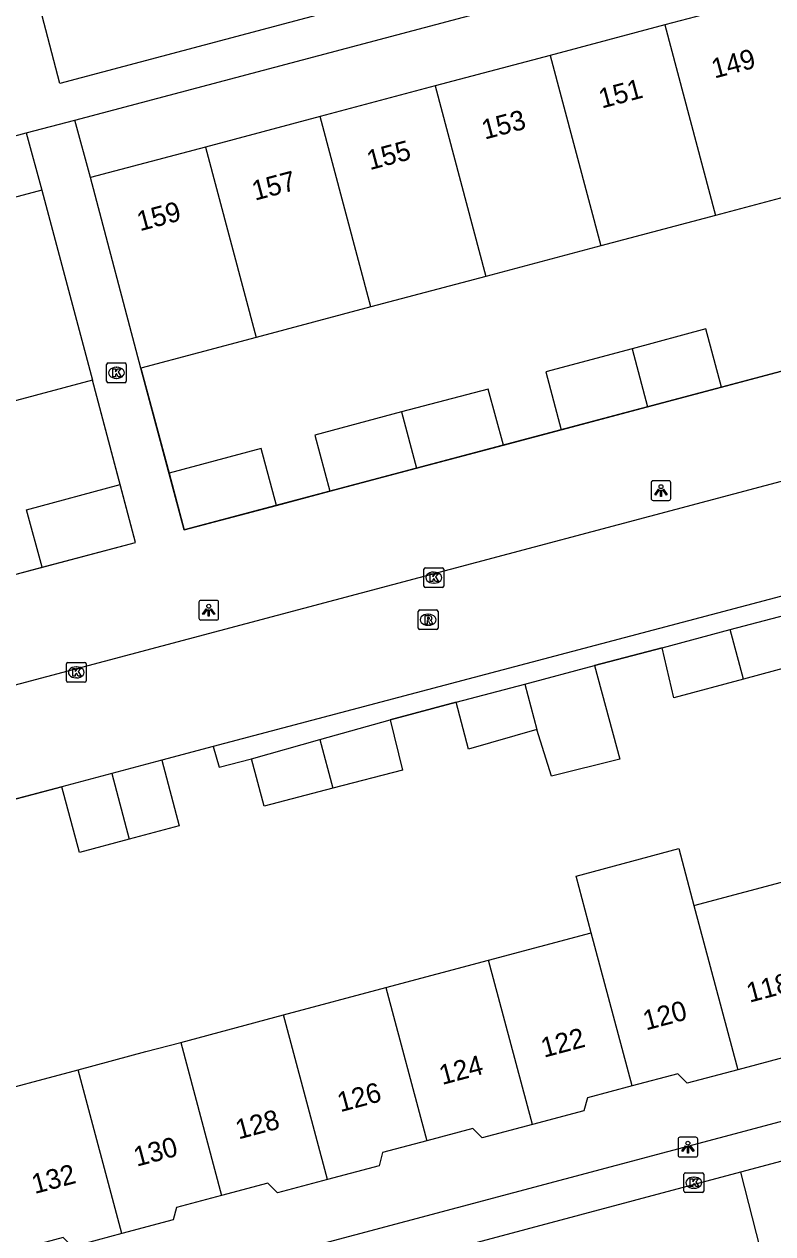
# Model space of a CAD drawing. Extents: x 162542 to 163144, y 380786 to 381511.
# Drawn here: x 162693.7 to 162731.7, y 381045.2 to 381106.6 of the extents above; entities that cross this region are included whole.
import ezdxf

# ---------------------------------------------------------------- set-up
doc = ezdxf.new("R2010")
doc.units = 0
for name, color, linetype in [('IMGEO_Kolk', 7, 'Continuous'), ('IMGEO_Lichtpunt', 7, 'Continuous'), ('IMGEO_Muur', 7, 'Continuous'), ('IMGEO_Pand', 7, 'Continuous'), ('IMGEO_Pand_nummerreeks', 7, 'Continuous'), ('IMGEO_Rijbaan_lokaal_open', 7, 'Continuous'), ('IMGEO_Rioolput', 7, 'Continuous'), ('IMGEO_Voetpad_open', 7, 'Continuous')]:
    doc.layers.add(name, color=color, linetype=linetype)

msp = doc.modelspace()

# ---------------------------------------------------------------- linework, layer by layer
at = {"layer": 'IMGEO_Kolk'}
for p, q in [((162697.906, 381088.473), (162697.906, 381089.325)), ((162697.981, 381089.399), (162698.833, 381089.399)), ((162698.394, 381089.179), (162698.419, 381089.179)), ((162698.907, 381089.325), (162698.907, 381088.473)), ((162698.417, 381088.619), (162698.392, 381088.619)), ((162698.833, 381088.399), (162697.981, 381088.399)), ((162713.998, 381078.083), (162713.998, 381078.935)), ((162714.073, 381079.009), (162714.925, 381079.009)), ((162714.486, 381078.789), (162714.511, 381078.789)), ((162714.999, 381078.935), (162714.999, 381078.083)), ((162714.925, 381078.009), (162714.073, 381078.009)), ((162714.509, 381078.229), (162714.484, 381078.229)), ((162695.868, 381073.28), (162695.868, 381074.132)), ((162695.943, 381074.206), (162696.795, 381074.206)), ((162696.356, 381073.986), (162696.381, 381073.986)), ((162696.869, 381074.132), (162696.869, 381073.28)), ((162696.795, 381073.206), (162695.943, 381073.206)), ((162696.379, 381073.426), (162696.354, 381073.426)), ((162727.182, 381047.392), (162727.182, 381048.244)), ((162727.257, 381048.318), (162728.109, 381048.318)), ((162727.67, 381048.098), (162727.695, 381048.098)), ((162728.183, 381048.244), (162728.183, 381047.392)), ((162728.109, 381047.318), (162727.257, 381047.318)), ((162727.693, 381047.538), (162727.668, 381047.538))]:
    msp.add_line(p, q, dxfattribs=at)
for points in [[(162697.906, 381088.473), (162697.906, 381089.325)], [(162697.981, 381089.399), (162698.833, 381089.399)], [(162698.227, 381089.099), (162698.35, 381089.099), (162698.35, 381088.948), (162698.48, 381089.099), (162698.644, 381089.099), (162698.498, 381088.948), (162698.651, 381088.699), (162698.499, 381088.699), (162698.414, 381088.863), (162698.35, 381088.796), (162698.35, 381088.699), (162698.227, 381088.699), (162698.227, 381089.099)], [(162698.907, 381089.325), (162698.907, 381088.473)], [(162698.833, 381088.399), (162697.981, 381088.399)], [(162713.998, 381078.083), (162713.998, 381078.935)], [(162714.073, 381079.009), (162714.925, 381079.009)], [(162714.319, 381078.709), (162714.442, 381078.709), (162714.442, 381078.558), (162714.572, 381078.709), (162714.736, 381078.709), (162714.59, 381078.558), (162714.743, 381078.309), (162714.591, 381078.309), (162714.506, 381078.473), (162714.442, 381078.406), (162714.442, 381078.309), (162714.319, 381078.309), (162714.319, 381078.709)], [(162714.999, 381078.935), (162714.999, 381078.083)], [(162714.925, 381078.009), (162714.073, 381078.009)], [(162695.868, 381073.28), (162695.868, 381074.132)], [(162695.943, 381074.206), (162696.795, 381074.206)], [(162696.189, 381073.906), (162696.312, 381073.906), (162696.312, 381073.755), (162696.442, 381073.906), (162696.606, 381073.906), (162696.46, 381073.755), (162696.613, 381073.506), (162696.461, 381073.506), (162696.376, 381073.67), (162696.312, 381073.603), (162696.312, 381073.506), (162696.189, 381073.506), (162696.189, 381073.906)], [(162696.869, 381074.132), (162696.869, 381073.28)], [(162696.795, 381073.206), (162695.943, 381073.206)], [(162727.182, 381047.392), (162727.182, 381048.244)], [(162727.257, 381048.318), (162728.109, 381048.318)], [(162727.503, 381048.018), (162727.626, 381048.018), (162727.626, 381047.867), (162727.756, 381048.018), (162727.92, 381048.018), (162727.774, 381047.867), (162727.927, 381047.618), (162727.775, 381047.618), (162727.69, 381047.782), (162727.626, 381047.715), (162727.626, 381047.618), (162727.503, 381047.618), (162727.503, 381048.018)], [(162728.183, 381048.244), (162728.183, 381047.392)], [(162728.109, 381047.318), (162727.257, 381047.318)]]:
    msp.add_lwpolyline(points, dxfattribs=at)
for centre, start, end in [((162697.983, 381089.323), 91.55205, 178.44795), ((162697.983, 381089.323), 91.55205, 178.44795), ((162698.831, 381089.323), 1.55205, 88.44795), ((162698.831, 381089.323), 1.55205, 88.44795), ((162697.983, 381088.475), 181.55205, 268.44795), ((162697.983, 381088.475), 181.55205, 268.44795), ((162698.831, 381088.475), 271.55205, 358.44795), ((162698.831, 381088.475), 271.55205, 358.44795), ((162714.075, 381078.933), 91.55205, 178.44795), ((162714.075, 381078.933), 91.55205, 178.44795), ((162714.923, 381078.933), 1.55205, 88.44795), ((162714.923, 381078.933), 1.55205, 88.44795), ((162714.075, 381078.085), 181.55205, 268.44795), ((162714.075, 381078.085), 181.55205, 268.44795), ((162714.923, 381078.085), 271.55205, 358.44795), ((162714.923, 381078.085), 271.55205, 358.44795), ((162695.945, 381074.13), 91.55205, 178.44795), ((162695.945, 381074.13), 91.55205, 178.44795), ((162696.793, 381074.13), 1.55205, 88.44795), ((162696.793, 381074.13), 1.55205, 88.44795), ((162695.945, 381073.282), 181.55205, 268.44795), ((162695.945, 381073.282), 181.55205, 268.44795), ((162696.793, 381073.282), 271.55205, 358.44795), ((162696.793, 381073.282), 271.55205, 358.44795), ((162727.259, 381048.242), 91.55205, 178.44795), ((162727.259, 381048.242), 91.55205, 178.44795), ((162728.107, 381048.242), 1.55205, 88.44795), ((162728.107, 381048.242), 1.55205, 88.44795), ((162727.259, 381047.394), 181.55205, 268.44795), ((162727.259, 381047.394), 181.55205, 268.44795), ((162728.107, 381047.394), 271.55205, 358.44795), ((162728.107, 381047.394), 271.55205, 358.44795)]:
    msp.add_arc(centre, 0.0765, start, end, dxfattribs=at)
for centre, major_axis, ratio, start_param, end_param in [((162698.393, 381088.899), (-0.387, 0.002), 0.722429, 4.712389, 7.853982), ((162698.418, 381088.899), (-0.39, 0.002), 0.717154, 1.570796, 4.712389), ((162714.485, 381078.509), (-0.387, 0.002), 0.722429, 4.712389, 7.853982), ((162714.51, 381078.509), (-0.39, 0.002), 0.717154, 1.570796, 4.712389), ((162696.355, 381073.706), (-0.387, 0.002), 0.722429, 4.712389, 7.853982), ((162696.38, 381073.706), (-0.39, 0.002), 0.717154, 1.570796, 4.712389), ((162727.669, 381047.818), (-0.387, 0.002), 0.722429, 4.712389, 7.853982), ((162727.694, 381047.818), (-0.39, 0.002), 0.717154, 1.570796, 4.712389)]:
    msp.add_ellipse(centre, major_axis=major_axis, ratio=ratio, start_param=start_param, end_param=end_param, dxfattribs=at)
at = {"layer": 'IMGEO_Lichtpunt'}
for p, q in [((162725.517, 381083.327), (162725.517, 381082.52)), ((162725.517, 381083.327), (162725.517, 381082.52)), ((162726.419, 381083.422), (162725.611, 381083.422)), ((162726.419, 381083.422), (162725.611, 381083.422)), ((162726.513, 381082.52), (162726.513, 381083.327)), ((162726.513, 381082.52), (162726.513, 381083.327)), ((162725.611, 381082.426), (162726.419, 381082.426)), ((162725.611, 381082.426), (162726.419, 381082.426)), ((162702.588, 381077.262), (162702.588, 381076.455)), ((162702.588, 381077.262), (162702.588, 381076.455)), ((162703.49, 381077.357), (162702.682, 381077.357)), ((162703.49, 381077.357), (162702.682, 381077.357)), ((162703.584, 381076.455), (162703.584, 381077.262)), ((162703.584, 381076.455), (162703.584, 381077.262)), ((162702.682, 381076.361), (162703.49, 381076.361)), ((162702.682, 381076.361), (162703.49, 381076.361)), ((162726.88, 381050.026), (162726.88, 381049.219)), ((162726.88, 381050.026), (162726.88, 381049.219)), ((162727.782, 381050.121), (162726.974, 381050.121)), ((162727.782, 381050.121), (162726.974, 381050.121)), ((162727.876, 381049.219), (162727.876, 381050.026)), ((162727.876, 381049.219), (162727.876, 381050.026)), ((162726.974, 381049.125), (162727.782, 381049.125)), ((162726.974, 381049.125), (162727.782, 381049.125))]:
    msp.add_line(p, q, dxfattribs=at)
for points in [[(162725.891, 381082.991), (162725.93, 381082.963), (162725.742, 381082.701), (162725.704, 381082.728), (162725.891, 381082.991)], [(162725.993, 381082.943), (162726.04, 381082.943), (162726.04, 381082.621), (162725.993, 381082.621), (162725.993, 381082.943)], [(162726.103, 381082.963), (162726.141, 381082.99), (162726.328, 381082.728), (162726.289, 381082.7), (162726.103, 381082.963)], [(162702.962, 381076.926), (162703.001, 381076.898), (162702.813, 381076.636), (162702.775, 381076.663), (162702.962, 381076.926)], [(162703.064, 381076.878), (162703.111, 381076.878), (162703.111, 381076.556), (162703.064, 381076.556), (162703.064, 381076.878)], [(162703.174, 381076.898), (162703.212, 381076.925), (162703.399, 381076.663), (162703.36, 381076.635), (162703.174, 381076.898)], [(162727.254, 381049.69), (162727.293, 381049.662), (162727.105, 381049.4), (162727.067, 381049.427), (162727.254, 381049.69)], [(162727.356, 381049.642), (162727.403, 381049.642), (162727.403, 381049.32), (162727.356, 381049.32), (162727.356, 381049.642)], [(162727.466, 381049.662), (162727.504, 381049.689), (162727.691, 381049.427), (162727.652, 381049.399), (162727.466, 381049.662)]]:
    msp.add_lwpolyline(points, dxfattribs=at)
for centre in [(162726.016, 381083.125), (162703.087, 381077.06), (162727.379, 381049.824)]:
    msp.add_circle(centre, 0.0994, dxfattribs=at)
for centre, start, end in [((162725.611, 381083.327), 90, 180), ((162725.611, 381083.327), 90, 180), ((162726.419, 381083.327), 0, 90), ((162726.419, 381083.327), 0, 90), ((162725.611, 381082.52), 180, 270), ((162725.611, 381082.52), 180, 270), ((162726.419, 381082.52), 270, 0), ((162726.419, 381082.52), 270, 360), ((162702.682, 381077.262), 90, 180), ((162702.682, 381077.262), 90, 180), ((162703.49, 381077.262), 0, 90), ((162703.49, 381077.262), 0, 90), ((162702.682, 381076.455), 180, 270), ((162702.682, 381076.455), 180, 270), ((162703.49, 381076.455), 270, 0), ((162703.49, 381076.455), 270, 360), ((162726.974, 381050.026), 90, 180), ((162726.974, 381050.026), 90, 180), ((162727.782, 381050.026), 0, 90), ((162727.782, 381050.026), 0, 90), ((162726.974, 381049.219), 180, 270), ((162726.974, 381049.219), 180, 270), ((162727.782, 381049.219), 270, 0), ((162727.782, 381049.219), 270, 360)]:
    msp.add_arc(centre, 0.0946, start, end, dxfattribs=at)
at = {"layer": 'IMGEO_Muur'}
for points in [[(162772.214, 381096.585), (162766.422, 381095.044), (162765.622, 381097.877), (162701.846, 381080.936)], [(162701.846, 381080.936), (162699.651, 381089.143)], [(162699.379, 381080.297), (162697.197, 381088.519)], [(162676.192, 381074.139), (162699.379, 381080.297)], [(162726.075, 381074.957), (162722.642, 381074.047)], [(162715.625, 381072.185), (162712.292, 381071.3)], [(162703.608, 381068.898), (162705.262, 381069.324)], [(162692.811, 381067.153), (162695.613, 381067.899)]]:
    msp.add_lwpolyline(points, dxfattribs=at)
at = {"layer": 'IMGEO_Pand'}
for points in [[(162732.042, 381108.097), (162726.216, 381106.548)], [(162726.216, 381106.548), (162720.391, 381104.999)], [(162726.216, 381106.548), (162728.785, 381096.887)], [(162720.391, 381104.999), (162714.565, 381103.451)], [(162720.391, 381104.999), (162722.959, 381095.339)], [(162714.565, 381103.451), (162708.739, 381101.902)], [(162714.565, 381103.451), (162717.134, 381093.79)], [(162708.739, 381101.902), (162702.914, 381100.353)], [(162711.308, 381092.241), (162708.739, 381101.902)], [(162702.914, 381100.353), (162697.083, 381098.802)], [(162702.914, 381100.353), (162705.482, 381090.693)], [(162699.651, 381089.143), (162697.083, 381098.802)], [(162734.611, 381098.436), (162728.785, 381096.887)], [(162694.624, 381098.159), (162688.799, 381096.606)], [(162694.624, 381098.159), (162697.197, 381088.519)], [(162728.785, 381096.887), (162722.959, 381095.339)], [(162722.959, 381095.339), (162717.134, 381093.79)], [(162717.134, 381093.79), (162711.308, 381092.241)], [(162711.308, 381092.241), (162705.482, 381090.693)], [(162729.082, 381088.171), (162728.289, 381091.13), (162724.548, 381090.117)], [(162705.482, 381090.693), (162699.651, 381089.143)], [(162724.548, 381090.117), (162720.171, 381088.943), (162720.958, 381086.013)], [(162724.548, 381090.117), (162725.331, 381087.174)], [(162697.197, 381088.519), (162691.363, 381086.964)], [(162718.023, 381085.233), (162717.261, 381088.078), (162712.865, 381086.914)], [(162725.331, 381087.174), (162729.082, 381088.171)], [(162712.865, 381086.914), (162708.467, 381085.734), (162709.227, 381082.897)], [(162712.865, 381086.914), (162713.622, 381084.064)], [(162720.958, 381086.013), (162725.331, 381087.174)], [(162706.517, 381082.177), (162705.745, 381085.057), (162701.078, 381083.807)], [(162713.622, 381084.064), (162718.023, 381085.233)], [(162701.078, 381083.807), (162701.846, 381080.936), (162706.517, 381082.177)], [(162709.227, 381082.897), (162713.622, 381084.064)], [(162694.634, 381079.037), (162693.851, 381081.956), (162698.601, 381083.229)], [(162694.634, 381079.037), (162699.379, 381080.297), (162698.601, 381083.229)], [(162729.524, 381075.872), (162732.998, 381076.794)], [(162732.998, 381076.794), (162733.623, 381074.293), (162730.194, 381073.368)], [(162726.075, 381074.957), (162729.524, 381075.872)], [(162730.194, 381073.368), (162729.524, 381075.872)], [(162730.194, 381073.368), (162726.674, 381072.419), (162726.075, 381074.957)], [(162719.111, 381073.11), (162722.642, 381074.047)], [(162722.642, 381074.047), (162723.934, 381069.306), (162720.472, 381068.431), (162719.726, 381070.809)], [(162715.625, 381072.185), (162719.111, 381073.11)], [(162719.111, 381073.11), (162719.726, 381070.809)], [(162719.726, 381070.809), (162716.258, 381069.811), (162715.625, 381072.185)], [(162708.711, 381070.294), (162712.292, 381071.3)], [(162712.292, 381071.3), (162712.904, 381068.75), (162709.37, 381067.829)], [(162705.262, 381069.324), (162708.711, 381070.294)], [(162708.711, 381070.294), (162709.37, 381067.829)], [(162700.7, 381069.254), (162698.168, 381068.579)], [(162700.7, 381069.254), (162701.59, 381065.914), (162699.058, 381065.238)], [(162709.37, 381067.829), (162705.894, 381066.923), (162705.262, 381069.324)], [(162698.168, 381068.579), (162695.634, 381067.905)], [(162698.168, 381068.579), (162699.058, 381065.238)], [(162699.058, 381065.238), (162696.526, 381064.563), (162695.634, 381067.905)], [(162722.483, 381060.491), (162721.715, 381063.375), (162726.92, 381064.763), (162727.689, 381061.879)], [(162727.689, 381061.879), (162732.893, 381063.267)], [(162727.689, 381061.879), (162729.914, 381053.551)], [(162717.278, 381059.103), (162722.483, 381060.491)], [(162724.558, 381052.727), (162722.483, 381060.491)], [(162712.073, 381057.714), (162717.278, 381059.103)], [(162719.504, 381050.774), (162717.278, 381059.103)], [(162706.868, 381056.326), (162712.073, 381057.714)], [(162712.073, 381057.714), (162714.149, 381049.947)], [(162701.663, 381054.938), (162706.868, 381056.326)], [(162709.101, 381047.974), (162706.868, 381056.326)], [(162734.968, 381055.505), (162732.669, 381054.892), (162732.493, 381054.239), (162729.914, 381053.551)], [(162696.458, 381053.55), (162699.889, 381054.465), (162701.663, 381054.938)], [(162701.663, 381054.938), (162703.739, 381047.171)], [(162691.254, 381052.162), (162696.458, 381053.55)], [(162698.68, 381045.234), (162696.458, 381053.55)], [(162729.914, 381053.551), (162727.341, 381052.865), (162726.864, 381053.342), (162724.558, 381052.727)], [(162724.558, 381052.727), (162722.288, 381052.122), (162722.112, 381051.47), (162719.504, 381050.774)], [(162719.504, 381050.774), (162716.953, 381050.093), (162716.479, 381050.568), (162714.149, 381049.947)], [(162714.149, 381049.947), (162711.901, 381049.347), (162711.719, 381048.673), (162709.101, 381047.974)], [(162709.101, 381047.974), (162706.571, 381047.299), (162706.077, 381047.794), (162703.739, 381047.171)], [(162703.739, 381047.171), (162701.456, 381046.562), (162701.286, 381045.929), (162698.68, 381045.234)], [(162698.68, 381045.234), (162696.171, 381044.565), (162695.706, 381045.031), (162693.329, 381044.397)]]:
    msp.add_lwpolyline(points, dxfattribs=at)
at = {"layer": 'IMGEO_Rijbaan_lokaal_open'}
for points in [[(162790.628, 381098.953), (162787.911, 381098.229), (162654.159, 381062.654)], [(162771.776, 381088.409), (162769.876, 381087.879), (162769.976, 381087.575), (162703.311, 381069.95)], [(162703.311, 381069.95), (162700.7, 381069.254)], [(162695.634, 381067.905), (162692.811, 381067.153)], [(162748.957, 381053.378), (162740.764, 381051.202), (162732.138, 381048.912), (162730.046, 381048.353)], [(162730.046, 381048.353), (162702.832, 381041.087)], [(162730.046, 381048.353), (162731.039, 381044.45)]]:
    msp.add_lwpolyline(points, dxfattribs=at)
at = {"layer": 'IMGEO_Rioolput'}
for p, q in [((162713.71, 381075.946), (162713.71, 381076.798)), ((162713.785, 381076.872), (162714.637, 381076.872)), ((162714.711, 381076.798), (162714.711, 381075.946)), ((162714.198, 381076.652), (162714.223, 381076.652)), ((162714.637, 381075.872), (162713.785, 381075.872)), ((162714.221, 381076.092), (162714.196, 381076.092))]:
    msp.add_line(p, q, dxfattribs=at)
for points in [[(162713.71, 381075.946), (162713.71, 381076.798)], [(162713.785, 381076.872), (162714.637, 381076.872)], [(162714.711, 381076.798), (162714.711, 381075.946)], [(162714.299, 381076.57), (162714.047, 381076.572), (162714.047, 381076.172)], [(162714.047, 381076.172), (162714.171, 381076.172), (162714.171, 381076.334), (162714.182, 381076.334)], [(162714.225, 381076.491), (162714.171, 381076.491), (162714.171, 381076.41)], [(162714.171, 381076.41), (162714.223, 381076.41)], [(162714.229, 381076.305), (162714.3, 381076.172), (162714.44, 381076.172), (162714.375, 381076.298)], [(162714.637, 381075.872), (162713.785, 381075.872)]]:
    msp.add_lwpolyline(points, dxfattribs=at)
for centre, radius, start, end in [((162713.787, 381076.796), 0.0765, 91.55205, 178.44795), ((162713.787, 381076.796), 0.0765, 91.55205, 178.44795), ((162714.635, 381076.796), 0.0765, 1.55205, 88.44795), ((162714.635, 381076.796), 0.0765, 1.55205, 88.44795), ((162714.181, 381076.281), 0.0533, 26.02933, 88.69889), ((162714.207, 381076.599), 0.19, 274.7715, 282.96867), ((162714.231, 381076.395), 0.0964, 77.00612, 93.18647), ((162714.245, 381076.452), 0.0378, 276.66336, 79.67722), ((162714.298, 381076.46), 0.109, 350.36119, 89.41601), ((162714.296, 381076.46), 0.112, 277.58423, 350.98172), ((162714.28, 381076.245), 0.108, 29.51342, 73.79051), ((162713.787, 381075.948), 0.0765, 181.55205, 268.44795), ((162713.787, 381075.948), 0.0765, 181.55205, 268.44795), ((162714.635, 381075.948), 0.0765, 271.55205, 358.44795), ((162714.635, 381075.948), 0.0765, 271.55205, 358.44795)]:
    msp.add_arc(centre, radius, start, end, dxfattribs=at)
for centre, major_axis, ratio, start_param, end_param in [((162714.197, 381076.372), (-0.387, 0.002), 0.722429, 4.712389, 7.853982), ((162714.222, 381076.372), (-0.39, 0.002), 0.717154, 1.570796, 4.712389)]:
    msp.add_ellipse(centre, major_axis=major_axis, ratio=ratio, start_param=start_param, end_param=end_param, dxfattribs=at)
at = {"layer": 'IMGEO_Voetpad_open'}
for points in [[(162696.302, 381101.71), (162760.455, 381118.748), (162765.901, 381120.189)], [(162712.824, 381108.171), (162711.256, 381107.755), (162695.539, 381103.583), (162694.038, 381109.357)], [(162693.826, 381101.081), (162696.302, 381101.71)], [(162697.083, 381098.802), (162696.302, 381101.71)], [(162664.86, 381093.347), (162670.32, 381094.788), (162684.374, 381098.519), (162693.826, 381101.081)], [(162693.826, 381101.081), (162694.624, 381098.159)], [(162699.651, 381089.143), (162701.078, 381083.807)], [(162729.082, 381088.171), (162732.633, 381089.114)], [(162698.601, 381083.229), (162697.197, 381088.519)], [(162718.023, 381085.233), (162720.958, 381086.013)], [(162706.517, 381082.177), (162709.227, 381082.897)], [(162692.103, 381078.365), (162694.634, 381079.037)], [(162722.642, 381074.047), (162726.075, 381074.957)], [(162712.292, 381071.3), (162715.625, 381072.185)], [(162703.311, 381069.95), (162703.608, 381068.898), (162705.262, 381069.324)], [(162703.09, 381041.562), (162702.691, 381043.093), (162731.566, 381050.786), (162754.912, 381057.05), (162759.948, 381058.339)]]:
    msp.add_lwpolyline(points, dxfattribs=at)

# ---------------------------------------------------------------- texts
at = {"layer": 'IMGEO_Pand_nummerreeks'}
for s, rotation, p in [('149', 14.88926, (162728.728, 381103.822)), ('151', 14.88926, (162723.012, 381102.302)), ('153', 14.88926, (162717.08, 381100.725)), ('155', 14.88926, (162711.254, 381099.176)), ('157', 14.88926, (162705.429, 381097.627)), ('159', 14.88926, (162699.597, 381096.077)), ('118', 14.98652, (162730.506, 381056.944)), ('120', 14.98652, (162725.255, 381055.538)), ('122', 14.98652, (162720.084, 381054.154)), ('124', 14.98652, (162714.922, 381052.772)), ('126', 14.98652, (162709.758, 381051.39)), ('128', 14.98652, (162704.598, 381050.008)), ('130', 14.98858, (162699.434, 381048.626)), ('132', 14.98652, (162694.264, 381047.241))]:
    msp.add_text(s, height=1, rotation=rotation, dxfattribs=at).set_placement(p)

doc.saveas('drawing.dxf')
